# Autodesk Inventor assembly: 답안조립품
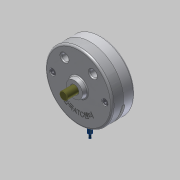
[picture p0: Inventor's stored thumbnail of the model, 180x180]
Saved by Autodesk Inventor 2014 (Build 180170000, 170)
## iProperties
Created: 2015-06
Part Number: 답안조립품
Document SubType Name: Assembly
Designer: MYHOME
Author: MYHOME
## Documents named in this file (10)
- C:\Documents and Settings\MYHOME\바탕 화면\450631V1038\답안조립품.iam
- C:\Documents and Settings\MYHOME\바탕 화면\450631V1038\본체.ipt
- C:\Documents and Settings\MYHOME\바탕 화면\450631V1038\덮개.ipt
- C:\Documents and Settings\MYHOME\바탕 화면\450631V1038\베어링62_22.ipt
- C:\Documents and Settings\MYHOME\바탕 화면\450631V1038\M10x35.ipt
- C:\Documents and Settings\MYHOME\바탕 화면\450631V1038\축.ipt
- C:\Documents and Settings\MYHOME\바탕 화면\450631V1038\멈춤링.ipt
- C:\Documents and Settings\MYHOME\바탕 화면\450631V1038\슬라이더2.ipt
- C:\Documents and Settings\MYHOME\바탕 화면\450631V1038\슬라이더.ipt
- C:\Documents and Settings\MYHOME\바탕 화면\450631V1038\평행핀.ipt
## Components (7 placed, 4 different names)
1. KS B 2023 62/22 - 22 x 50 x 14:1 — 각도:3
2. KS B 2023 62/22 - 22 x 50 x 14:2
3. KS B 1003 - 미터 M 10 x 35:1
4. KS B 1003 - 미터 M 10 x 35:2
5. KS B 1336 22 x 1.2:1 — 각도:1
6. KS B 1336 22 x 1.2:2 — 각도:2
7. KS B 1320 B B 5 x  20:1
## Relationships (3: Angle 3)
- 각도:1 [Angle]: KS B 1336 22 x 1.2:1
- 각도:2 [Angle]: KS B 1336 22 x 1.2:2
- 각도:3 [Angle]: KS B 2023 62/22 - 22 x 50 x 14:1
